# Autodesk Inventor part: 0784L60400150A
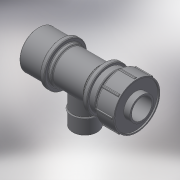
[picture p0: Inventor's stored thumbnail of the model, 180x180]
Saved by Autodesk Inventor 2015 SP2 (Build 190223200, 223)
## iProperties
Created: 2018-02
Part Number: 0784L60400150A
Material: Generic
Description: PLASSON MODULAR MALE TEE 40-1.1/2"-40
Document SubType Name: Modeling
Designer: KIM
Density: 1 g/cm^3
Appearance: Default
Author: KIM
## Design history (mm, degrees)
derived "0784L6.ipt"
feature "Solid1::0784L6.ipt"
feature "Solid2::0784L6.ipt"
tag "TaggingFeature1"
body "Solid1"
other parameters: "d26" = 38.55665, "d51" = 2, "d52" = 4.1, "d54" = 0, "d55" = 2, "d56" = 1, "d58" = 360 deg, "d60" = 1, "d63" = 1, "d65" = 0, "d67" = 0, "d69" = 158, "d70" = 71, "d71" = 47.803, "d73" = 79.54, "d74" = 64, "d75" = 35, "d76" = 75.44, "d77" = 36, "d79" = 37.2, "d80" = 34, "d82" = 7, "d83" = 73.8, "d84" = 73.8, "d86" = 61.5, "d88" = 65.6, "d89" = 57.4, "d90" = 9, "d91" = 34.2, "d92" = 69.7, "d93" = 39.6, "d94" = 32.4, "d95" = 7.2, "d96" = 48.6, "d97" = 47.4, "d98" = 57.4, "d99" = 41, "d100" = 36.9, "d101" = 22, "d102" = 35.85225, "d103" = 52.5833, "d104" = 24.2, "E_" = 82, "H_" = 158, "l_1" = 36, "l_2" = 22, "A_" = 71, "d_" = 1, "R_" = 47.803, "ODP_" = 64, "LPT_" = 35
